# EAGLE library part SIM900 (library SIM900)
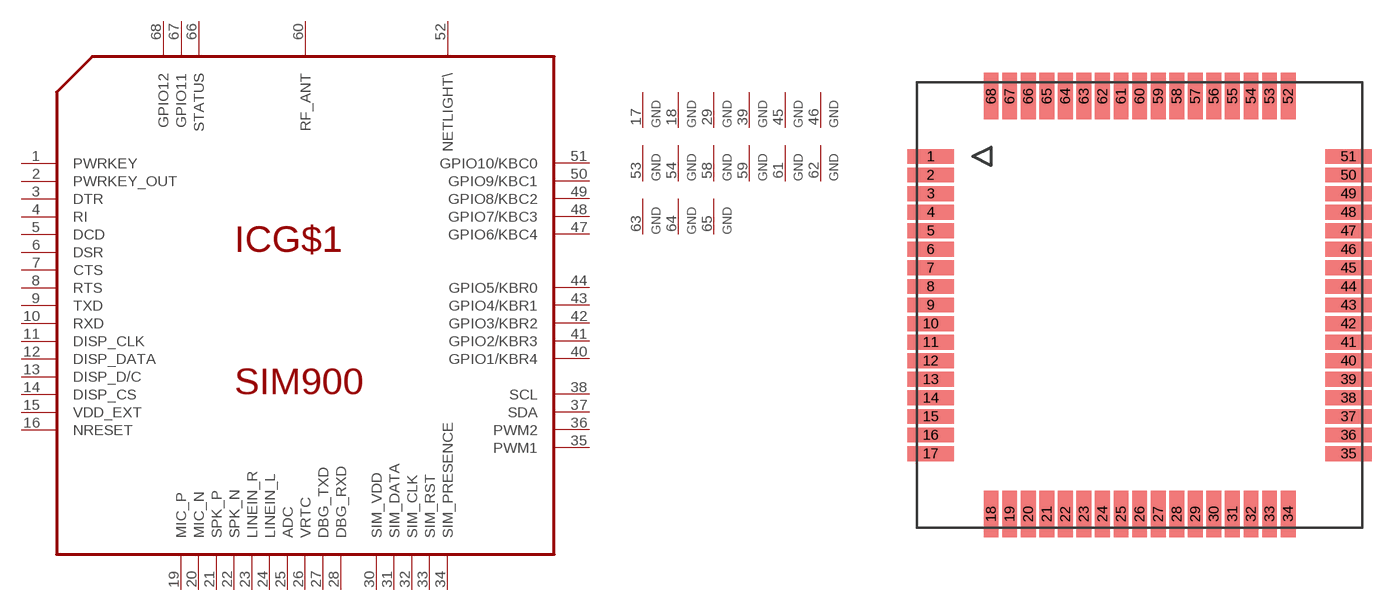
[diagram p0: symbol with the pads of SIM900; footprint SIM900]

Designator prefix IC; gates G$1=SIM900 GND@1=GND GND@2=GND GND@3=GND GND@4=GND GND@5=GND GND@6=GND GND@7=GND GND@8=GND GND@9=GND GND@10=GND GND@11=GND GND@12=GND GND@13=GND GND@14=GND GND@15=GND VBAT@1=VBAT VBAT@2=VBAT VBAT@3=VBAT

## SIM900  [SIM900]
1  G$1:PWRKEY
2  G$1:PWRKEY_OUT
3  G$1:DTR
4  G$1:RI
5  G$1:DCD
6  G$1:DSR
7  G$1:CTS
8  G$1:RTS
9  G$1:TXD
10  G$1:RXD
11  G$1:DISP_CLK
12  G$1:DISP_DATA
13  G$1:DISP_D/C
14  G$1:DISP_CS
15  G$1:VDD_EXT
16  G$1:NRESET
17  GND@1:GND  pwr
18  GND@2:GND  pwr
19  G$1:MIC_P
20  G$1:MIC_N
21  G$1:SPK_P
22  G$1:SPK_N
23  G$1:LINEIN_R
24  G$1:LINEIN_L
25  G$1:ADC
26  G$1:VRTC
27  G$1:DBG_TXD
28  G$1:DBG_RXD
29  GND@3:GND  pwr
30  G$1:SIM_VDD
31  G$1:SIM_DATA
32  G$1:SIM_CLK
33  G$1:SIM_RST
34  G$1:SIM_PRESENCE
35  G$1:PWM1
36  G$1:PWM2
37  G$1:SDA
38  G$1:SCL
39  GND@4:GND  pwr
40  G$1:GPIO1/KBR4
41  G$1:GPIO2/KBR3
42  G$1:GPIO3/KBR2
43  G$1:GPIO4/KBR1
44  G$1:GPIO5/KBR0
45  GND@5:GND  pwr
46  GND@6:GND  pwr
47  G$1:GPIO6/KBC4
48  G$1:GPIO7/KBC3
49  G$1:GPIO8/KBC2
50  G$1:GPIO9/KBC1
51  G$1:GPIO10/KBC0
52  G$1:NETLIGHT\
53  GND@7:GND  pwr
54  GND@8:GND  pwr
55  VBAT@1:VBAT  pwr
56  VBAT@2:VBAT  pwr
57  VBAT@3:VBAT  pwr
58  GND@9:GND  pwr
59  GND@10:GND  pwr
60  G$1:RF_ANT
61  GND@11:GND  pwr
62  GND@12:GND  pwr
63  GND@13:GND  pwr
64  GND@14:GND  pwr
65  GND@15:GND  pwr
66  G$1:STATUS
67  G$1:GPIO11
68  G$1:GPIO12

## Footprint SIM900 (pad centres in mm)
smd 2.5 x 0.8: 1 -11.25,8; 2 -11.25,7; 3 -11.25,6; 4 -11.25,5; 5 -11.25,4; 6 -11.25,3; 7 -11.25,2; 8 -11.25,1; 9 -11.25,0; 10 -11.25,-1; 11 -11.25,-2; 12 -11.25,-3; 13 -11.25,-4; 14 -11.25,-5; 15 -11.25,-6; 16 -11.25,-7; 17 -11.25,-8; 35 11.25,-8; 36 11.25,-7; 37 11.25,-6; 38 11.25,-5; 39 11.25,-4; 40 11.25,-3; 41 11.25,-2; 42 11.25,-1; 43 11.25,0; 44 11.25,1; 45 11.25,2; 46 11.25,3; 47 11.25,4; 48 11.25,5; 49 11.25,6; 50 11.25,7; 51 11.25,8
smd 0.8 x 2.5: 18 -8,-11.25; 19 -7,-11.25; 20 -6,-11.25; 21 -5,-11.25; 22 -4,-11.25; 23 -3,-11.25; 24 -2,-11.25; 25 -1,-11.25; 26 0,-11.25; 27 1,-11.25; 28 2,-11.25; 29 3,-11.25; 30 4,-11.25; 31 5,-11.25; 32 6,-11.25; 33 7,-11.25; 34 8,-11.25; 52 8,11.25; 53 7,11.25; 54 6,11.25; 55 5,11.25; 56 4,11.25; 57 3,11.25; 58 2,11.25; 59 1,11.25; 60 0,11.25; 61 -1,11.25; 62 -2,11.25; 63 -3,11.25; 64 -4,11.25; 65 -5,11.25; 66 -6,11.25; 67 -7,11.25; 68 -8,11.25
